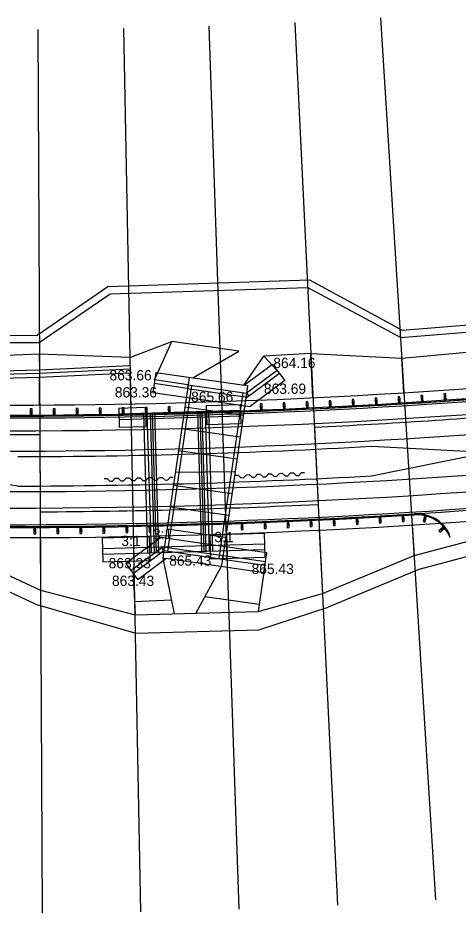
# Model space of a CAD drawing. Extents: x 223098 to 226975, y 386666 to 387582.
# Drawn here: x 223877.2 to 223996.7, y 387140.9 to 387384.1 of the extents above; entities that cross this region are included whole.
import ezdxf

# ---------------------------------------------------------------- set-up
doc = ezdxf.new("R2010")
doc.units = 0
for name, color, linetype in [('_CIVIL_CONSTRUCTION', 7, 'Continuous'), ('AP_X_Airspace', 7, 'Continuous'), ('BD_X_Building', 7, 'Continuous'), ('Default', 7, 'Continuous'), ('DR_X_Ditch', 7, 'Continuous'), ('DR_X_Erosion_Control', 7, 'Continuous'), ('DR_X_Headwall', 7, 'Continuous'), ('PF_X_Ground_Line', 7, 'Continuous'), ('PV_X_COP', 7, 'Continuous'), ('PV_X_Driveway', 7, 'Continuous'), ('PV_X_Shoulder', 7, 'Continuous'), ('PV_X_Shoulder_Aggregate', 7, 'Continuous'), ('RW_X_CL_100_Distances', 7, 'Continuous'), ('SV_X_Toe_of_Slope', 7, 'Continuous'), ('SV_X_Top_of_Bank', 7, 'Continuous'), ('UT_X_Gas_Cells', 7, 'Continuous'), ('UT_X_Water_Cells', 7, 'Continuous'), ('VG_X_Cells', 7, 'Continuous')]:
    doc.layers.add(name, color=color, linetype=linetype)

msp = doc.modelspace()

# ---------------------------------------------------------------- linework, layer by layer
at = {"layer": '_CIVIL_CONSTRUCTION'}
for p, q in [((223904.6, 387278.11), (223911.84, 387278.32)), ((223904.6, 387278.11), (223904.75, 387272.92)), ((223904.64, 387276.55), (223937.63, 387277.5)), ((223911.84, 387278.32), (223911.99, 387273.13)), ((223925.97, 387277.16), (223927.07, 387239.23)), ((223926.63, 387277.18), (223927.73, 387239.25)), ((223927.18, 387277.2), (223928.27, 387239.27)), ((223928.01, 387277.22), (223929.11, 387239.29)), ((223928.34, 387278.8), (223937.58, 387279.06)), ((223928.34, 387278.8), (223928.49, 387273.61)), ((223928.97, 387277.25), (223930.07, 387239.32)), ((223937.58, 387279.06), (223937.73, 387273.88)), ((223904.69, 387275.05), (223937.67, 387276)), ((223911.3, 387276.74), (223912.4, 387238.81)), ((223912.26, 387276.77), (223913.36, 387238.84)), ((223913.09, 387276.79), (223914.19, 387238.86)), ((223913.64, 387276.81), (223914.74, 387238.88)), ((223914.3, 387276.83), (223915.4, 387238.9)), ((223904.75, 387272.92), (223911.99, 387273.13)), ((223928.49, 387273.61), (223937.73, 387273.88)), ((223900.12, 387242.83), (223912.86, 387243.2)), ((223912.86, 387243.2), (223913.05, 387236.7)), ((223929.35, 387243.68), (223944.1, 387244.1)), ((223929.35, 387243.68), (223929.54, 387237.18)), ((223944.1, 387244.1), (223944.28, 387237.61)), ((223900.12, 387242.83), (223900.3, 387236.33)), ((223900.2, 387239.96), (223944.18, 387241.23)), ((223900.24, 387238.46), (223944.22, 387239.73)), ((223900.3, 387236.33), (223913.05, 387236.7)), ((223929.54, 387237.18), (223944.28, 387237.61))]:
    msp.add_line(p, q, dxfattribs=at)
at = {"layer": 'AP_X_Airspace'}
for points in [[(223936.25, 387259.88), (223937, 387259.91), (223937.78, 387259.19), (223938.53, 387259.22), (223939.25, 387260), (223940, 387260.03), (223940.78, 387259.31), (223941.53, 387259.34), (223942.25, 387260.12), (223943, 387260.15), (223943.77, 387259.43), (223944.52, 387259.46), (223945.24, 387260.24), (223945.99, 387260.27)], [(223945.24, 387260.24), (223945.99, 387260.27), (223946.77, 387259.55), (223947.52, 387259.58), (223948.24, 387260.36), (223948.99, 387260.39), (223949.77, 387259.67), (223950.52, 387259.7), (223951.24, 387260.48), (223951.99, 387260.51), (223952.77, 387259.79), (223953.52, 387259.82), (223954.24, 387260.6), (223954.99, 387260.63)], [(223900.66, 387259.01), (223901.41, 387259.02), (223902.17, 387258.29), (223902.92, 387258.3), (223903.66, 387259.07), (223904.41, 387259.08), (223905.17, 387258.34), (223905.92, 387258.36), (223906.66, 387259.12), (223907.41, 387259.14), (223908.17, 387258.4), (223908.92, 387258.41), (223909.66, 387259.18), (223910.41, 387259.19)], [(223909.66, 387259.18), (223910.41, 387259.19), (223911.17, 387258.46), (223911.92, 387258.47), (223912.66, 387259.23), (223913.41, 387259.25), (223914.17, 387258.51), (223914.92, 387258.53), (223915.66, 387259.29), (223916.41, 387259.3), (223917.17, 387258.57), (223917.92, 387258.58), (223918.66, 387259.35), (223919.41, 387259.36)]]:
    msp.add_lwpolyline(points, dxfattribs=at)
at = {"layer": 'BD_X_Building'}
for p, q in [((223883.03, 387295.94), (223902.27, 387309.15)), ((223902.27, 387309.15), (223955.87, 387310.88)), ((223981.08, 387297.25), (223955.87, 387310.88)), ((223981.08, 387297.25), (224104.98, 387307.24)), ((223809.49, 387295.84), (223883.03, 387295.94))]:
    msp.add_line(p, q, dxfattribs=at)
at = {"layer": 'Default'}
for p, q in [((223975.67, 387384.08), (223990.61, 387144.55)), ((223937.25, 387141.98), (223929.15, 387381.85)), ((223952.42, 387382.8), (223963.94, 387143.08)), ((223882.59, 387380.94), (223883.83, 387140.94)), ((223905.87, 387381.23), (223910.54, 387141.27))]:
    msp.add_line(p, q, dxfattribs=at)
at = {"layer": 'DR_X_Ditch'}
for p, q in [((223963.27, 387247.89), (223962.82, 387246.87)), ((223969.01, 387248.19), (223969.56, 387247.22)), ((223969.51, 387248.22), (223969.06, 387247.19)), ((223975.25, 387248.54), (223975.81, 387247.57)), ((223975.75, 387248.56), (223975.31, 387247.54)), ((223981.49, 387248.9), (223982.05, 387247.94)), ((223981.99, 387248.94), (223981.55, 387247.91)), ((223988.11, 387248.77), (223987.38, 387247.92)), ((223987.63, 387248.89), (223987.87, 387247.8)), ((223881.54, 387245.65), (223882.05, 387244.66)), ((223882.04, 387245.66), (223881.55, 387244.65)), ((223887.79, 387245.69), (223888.3, 387244.7)), ((223888.29, 387245.69), (223887.8, 387244.69)), ((223894.04, 387245.75), (223894.55, 387244.76)), ((223894.54, 387245.76), (223894.05, 387244.75)), ((223900.29, 387245.83), (223900.81, 387244.84)), ((223900.79, 387245.84), (223900.31, 387244.83)), ((223906.54, 387245.94), (223907.06, 387244.95)), ((223907.04, 387245.94), (223906.56, 387244.94)), ((223912.79, 387246.06), (223913.31, 387245.07)), ((223913.29, 387246.07), (223912.81, 387245.06)), ((223937.79, 387246.79), (223938.32, 387245.8)), ((223938.29, 387246.8), (223937.82, 387245.79)), ((223944.03, 387247.02), (223944.57, 387246.04)), ((223944.53, 387247.04), (223944.07, 387246.02)), ((223950.28, 387247.28), (223950.82, 387246.3)), ((223950.78, 387247.3), (223950.32, 387246.28)), ((223956.52, 387247.56), (223957.07, 387246.59)), ((223957.02, 387247.58), (223956.57, 387246.56)), ((223962.77, 387247.86), (223963.32, 387246.89)), ((223993.09, 387245.45), (223992, 387245.2)), ((223992.77, 387245.84), (223992.32, 387244.81)), ((223994.51, 387242.97), (223994.41, 387243.9))]:
    msp.add_line(p, q, dxfattribs=at)
for points in [[(223962.82, 387246.87), (223963.32, 387246.89), (223963.27, 387247.89), (223962.77, 387247.86)], [(223969.06, 387247.19), (223969.56, 387247.22), (223969.51, 387248.22), (223969.01, 387248.19)], [(223975.31, 387247.54), (223975.81, 387247.57), (223975.75, 387248.56), (223975.25, 387248.54)], [(223981.55, 387247.91), (223982.05, 387247.94), (223981.99, 387248.94), (223981.49, 387248.9)], [(223981.59, 387247.24), (223982.09, 387247.27), (223982.05, 387247.94), (223981.55, 387247.91)], [(223987.22, 387247.28), (223987.7, 387247.15), (223987.87, 387247.8), (223987.38, 387247.92)], [(223987.38, 387247.92), (223987.87, 387247.8), (223988.11, 387248.77), (223987.63, 387248.89)], [(223881.55, 387244.65), (223882.05, 387244.66), (223882.04, 387245.66), (223881.54, 387245.65)], [(223887.8, 387244.69), (223888.3, 387244.7), (223888.29, 387245.69), (223887.79, 387245.69)], [(223894.05, 387244.75), (223894.55, 387244.76), (223894.54, 387245.76), (223894.04, 387245.75)], [(223900.31, 387244.83), (223900.81, 387244.84), (223900.79, 387245.84), (223900.29, 387245.83)], [(223906.56, 387244.94), (223907.06, 387244.95), (223907.04, 387245.94), (223906.54, 387245.94)], [(223912.81, 387245.06), (223913.31, 387245.07), (223913.29, 387246.07), (223912.79, 387246.06)], [(223937.82, 387245.79), (223938.32, 387245.8), (223938.29, 387246.8), (223937.79, 387246.79)], [(223937.85, 387245.12), (223938.35, 387245.14), (223938.32, 387245.8), (223937.82, 387245.79)], [(223944.07, 387246.02), (223944.57, 387246.04), (223944.53, 387247.04), (223944.03, 387247.02)], [(223944.1, 387245.36), (223944.6, 387245.38), (223944.57, 387246.04), (223944.07, 387246.02)], [(223950.32, 387246.28), (223950.82, 387246.3), (223950.78, 387247.3), (223950.28, 387247.28)], [(223950.35, 387245.62), (223950.85, 387245.64), (223950.82, 387246.3), (223950.32, 387246.28)], [(223956.57, 387246.56), (223957.07, 387246.59), (223957.02, 387247.58), (223956.52, 387247.56)], [(223956.6, 387245.9), (223957.1, 387245.92), (223957.07, 387246.59), (223956.57, 387246.56)], [(223962.85, 387246.2), (223963.35, 387246.22), (223963.32, 387246.89), (223962.82, 387246.87)], [(223969.1, 387246.52), (223969.6, 387246.55), (223969.56, 387247.22), (223969.06, 387247.19)], [(223975.35, 387246.87), (223975.85, 387246.9), (223975.81, 387247.57), (223975.31, 387247.54)], [(223992, 387245.2), (223992.32, 387244.81), (223993.09, 387245.45), (223992.77, 387245.84)], [(223881.55, 387243.99), (223882.05, 387243.99), (223882.05, 387244.66), (223881.55, 387244.65)], [(223887.8, 387244.02), (223888.3, 387244.03), (223888.3, 387244.7), (223887.8, 387244.69)], [(223894.06, 387244.08), (223894.56, 387244.09), (223894.55, 387244.76), (223894.05, 387244.75)], [(223900.32, 387244.17), (223900.82, 387244.17), (223900.81, 387244.84), (223900.31, 387244.83)], [(223906.57, 387244.27), (223907.07, 387244.28), (223907.06, 387244.95), (223906.56, 387244.94)], [(223912.83, 387244.4), (223913.33, 387244.41), (223913.31, 387245.07), (223912.81, 387245.06)], [(223991.49, 387244.77), (223991.81, 387244.38), (223992.32, 387244.81), (223992, 387245.2)]]:
    msp.add_lwpolyline(points, close=True, dxfattribs=at)
for centre, radius, start, end in [((223874.12, 389011.68), 1766.04, 267.16046, 273.59506), ((223874.12, 389011.68), 1765.76, 267.16046, 273.59495), ((223985.47, 387239.41), 10, 26.6312, 93.595), ((223985.47, 387239.41), 9.72, 21.457, 93.595)]:
    msp.add_arc(centre, radius, start, end, dxfattribs=at)
at = {"layer": 'DR_X_Erosion_Control'}
for p, q in [((223882.02, 387224.88), (223909.22, 387216.93)), ((223942.59, 387217.86), (223961.4, 387224.07)), ((223909.22, 387216.93), (223942.59, 387217.86))]:
    msp.add_line(p, q, dxfattribs=at)
for points in [[(223784.61, 387295.04), (223809.49, 387297.84), (223882.41, 387297.94), (223901.62, 387311.13), (223956.35, 387312.9), (223981.51, 387299.29), (224105.08, 387309.26), (224183.43, 387294.86)], [(224029.67, 387236.44), (224009.82, 387240.6), (223986.06, 387234.3), (223961.4, 387224.07)], [(223882.02, 387224.88), (223857.12, 387236.46), (223832.67, 387236.64), (223807.35, 387237.15), (223782.08, 387237.65), (223757.07, 387238.34)]]:
    msp.add_lwpolyline(points, dxfattribs=at)
at = {"layer": 'DR_X_Headwall'}
msp.add_lwpolyline([(223907.67, 387288.69), (223883.07, 387287.49), (223858.44, 387286.89), (223833.81, 387286.93), (223809.14, 387286.48), (223784.41, 387286.67), (223759.3, 387285.04)], dxfattribs=at)
at = {"layer": 'PF_X_Ground_Line'}
msp.add_line((223973.16, 387267.73), (224045.07, 387264.09), dxfattribs=at)
for radius, start, end in [(1736.26, 268.92281, 274.61725), (1745.26, 268.92281, 274.61725), (1746.76, 270.10137, 273.25028)]:
    msp.add_arc((223874.12, 389011.68), radius, start, end, dxfattribs=at)
at = {"layer": 'PV_X_COP'}
for p, q in [((223924.68, 387286.34), (223937.23, 387293.53)), ((223938.54, 387284.34), (223944, 387292.22)), ((223916.59, 387237.33), (223919.65, 387222.23)), ((223932.42, 387235.04), (223925.55, 387222.39))]:
    msp.add_line(p, q, dxfattribs=at)
at = {"layer": 'PV_X_Driveway'}
for p, q in [((223968.52, 387278.77), (223967.97, 387279.74)), ((223968.02, 387278.74), (223968.47, 387279.77)), ((223974.76, 387279.12), (223974.2, 387280.09)), ((223974.26, 387279.09), (223974.7, 387280.12)), ((223981, 387279.49), (223980.44, 387280.46)), ((223980.5, 387279.46), (223980.94, 387280.49)), ((223987.23, 387279.89), (223986.67, 387280.86)), ((223986.73, 387279.86), (223987.17, 387280.89)), ((223993.47, 387280.31), (223992.9, 387281.27)), ((223992.97, 387280.27), (223993.4, 387281.31)), ((223881.08, 387276.21), (223880.58, 387277.21)), ((223880.58, 387276.21), (223881.08, 387277.21)), ((223887.33, 387276.25), (223886.82, 387277.25)), ((223886.83, 387276.25), (223887.32, 387277.25)), ((223893.58, 387276.31), (223893.07, 387277.3)), ((223893.08, 387276.3), (223893.57, 387277.31)), ((223899.83, 387276.39), (223899.31, 387277.38)), ((223899.33, 387276.38), (223899.81, 387277.39)), ((223906.07, 387276.49), (223905.56, 387277.49)), ((223905.57, 387276.49), (223906.06, 387277.49)), ((223912.32, 387276.62), (223911.8, 387277.61)), ((223911.82, 387276.61), (223912.3, 387277.62)), ((223918.57, 387276.77), (223918.04, 387277.76)), ((223918.07, 387276.76), (223918.54, 387277.77)), ((223943.55, 387277.59), (223943.01, 387278.57)), ((223943.05, 387277.57), (223943.51, 387278.59)), ((223949.8, 387277.85), (223949.25, 387278.83)), ((223949.3, 387277.83), (223949.75, 387278.85)), ((223956.04, 387278.13), (223955.49, 387279.11)), ((223955.54, 387278.11), (223955.99, 387279.13)), ((223962.28, 387278.44), (223961.73, 387279.41)), ((223961.78, 387278.42), (223962.23, 387279.44))]:
    msp.add_line(p, q, dxfattribs=at)
for points in [[(223993.35, 387281.97), (223992.85, 387281.94), (223992.9, 387281.27), (223993.4, 387281.31)], [(223949.72, 387279.52), (223949.22, 387279.49), (223949.25, 387278.83), (223949.75, 387278.85)], [(223955.96, 387279.8), (223955.46, 387279.78), (223955.49, 387279.11), (223955.99, 387279.13)], [(223962.19, 387280.11), (223961.7, 387280.08), (223961.73, 387279.41), (223962.23, 387279.44)], [(223968.43, 387280.43), (223967.93, 387280.41), (223967.97, 387279.74), (223968.47, 387279.77)], [(223968.47, 387279.77), (223967.97, 387279.74), (223968.02, 387278.74), (223968.52, 387278.77)], [(223974.66, 387280.78), (223974.16, 387280.76), (223974.2, 387280.09), (223974.7, 387280.12)], [(223974.7, 387280.12), (223974.2, 387280.09), (223974.26, 387279.09), (223974.76, 387279.12)], [(223980.89, 387281.16), (223980.4, 387281.13), (223980.44, 387280.46), (223980.94, 387280.49)], [(223980.94, 387280.49), (223980.44, 387280.46), (223980.5, 387279.46), (223981, 387279.49)], [(223987.12, 387281.55), (223986.63, 387281.52), (223986.67, 387280.86), (223987.17, 387280.89)], [(223987.17, 387280.89), (223986.67, 387280.86), (223986.73, 387279.86), (223987.23, 387279.89)], [(223993.4, 387281.31), (223992.9, 387281.27), (223992.97, 387280.27), (223993.47, 387280.31)], [(223881.07, 387277.88), (223880.57, 387277.88), (223880.58, 387277.21), (223881.08, 387277.21)], [(223881.08, 387277.21), (223880.58, 387277.21), (223880.58, 387276.21), (223881.08, 387276.21)], [(223887.32, 387277.92), (223886.82, 387277.91), (223886.82, 387277.25), (223887.32, 387277.25)], [(223887.32, 387277.25), (223886.82, 387277.25), (223886.83, 387276.25), (223887.33, 387276.25)], [(223893.56, 387277.98), (223893.06, 387277.97), (223893.07, 387277.3), (223893.57, 387277.31)], [(223893.57, 387277.31), (223893.07, 387277.3), (223893.08, 387276.3), (223893.58, 387276.31)], [(223899.8, 387278.06), (223899.3, 387278.05), (223899.31, 387277.38), (223899.81, 387277.39)], [(223899.81, 387277.39), (223899.31, 387277.38), (223899.33, 387276.38), (223899.83, 387276.39)], [(223906.04, 387278.16), (223905.54, 387278.15), (223905.56, 387277.49), (223906.06, 387277.49)], [(223906.06, 387277.49), (223905.56, 387277.49), (223905.57, 387276.49), (223906.07, 387276.49)], [(223912.29, 387278.29), (223911.79, 387278.28), (223911.8, 387277.61), (223912.3, 387277.62)], [(223912.3, 387277.62), (223911.8, 387277.61), (223911.82, 387276.61), (223912.32, 387276.62)], [(223918.53, 387278.44), (223918.03, 387278.42), (223918.04, 387277.76), (223918.54, 387277.77)], [(223918.54, 387277.77), (223918.04, 387277.76), (223918.07, 387276.76), (223918.57, 387276.77)], [(223943.49, 387279.26), (223942.99, 387279.24), (223943.01, 387278.57), (223943.51, 387278.59)], [(223943.51, 387278.59), (223943.01, 387278.57), (223943.05, 387277.57), (223943.55, 387277.59)], [(223949.75, 387278.85), (223949.25, 387278.83), (223949.3, 387277.83), (223949.8, 387277.85)], [(223955.99, 387279.13), (223955.49, 387279.11), (223955.54, 387278.11), (223956.04, 387278.13)], [(223962.23, 387279.44), (223961.73, 387279.41), (223961.78, 387278.42), (223962.28, 387278.44)]]:
    msp.add_lwpolyline(points, close=True, dxfattribs=at)
for radius, start in [(1735.48, 269.08669), (1735.76, 269.08671)]:
    msp.add_arc((223874.12, 389011.68), radius, start, 274.7899, dxfattribs=at)
at = {"layer": 'PV_X_Shoulder'}
for p, q in [((223914.32, 387285.74), (223919.02, 387296.16)), ((223937.23, 387293.53), (223919.02, 387296.16)), ((223944, 387292.22), (223947.59, 387288.31)), ((223944.27, 387235.43), (223942.45, 387222.86)), ((223908.52, 387233.22), (223909.08, 387221.93)), ((223909.08, 387221.93), (223942.45, 387222.86))]:
    msp.add_line(p, q, dxfattribs=at)
at = {"layer": 'PV_X_Shoulder_Aggregate'}
for p, q in [((223946.34, 387289.98), (223938.76, 387284.31)), ((223946.34, 387289.98), (223949.64, 387285.57)), ((223914.62, 387287.8), (223913.84, 387282.36)), ((223914.62, 387287.8), (223938.76, 387284.31)), ((223947.59, 387288.31), (223939.31, 387282.12)), ((223948.19, 387287.51), (223939.58, 387281.07)), ((223923.17, 387283.45), (223914.18, 387284.75)), ((223923.31, 387284.44), (223914.32, 387285.74)), ((223923.4, 387284.43), (223916.88, 387239.39)), ((223923.31, 387284.44), (223923.17, 387283.45)), ((223923.31, 387284.44), (223939.31, 387282.12)), ((223923.69, 387286.49), (223923.4, 387284.43)), ((223949.64, 387285.57), (223940.23, 387278.54)), ((223913.84, 387282.36), (223940.23, 387278.54)), ((223924.39, 387284.28), (223917.87, 387239.25)), ((223923.17, 387283.45), (223939.58, 387281.07)), ((223938.24, 387282.28), (223931.73, 387237.25)), ((223939.23, 387282.14), (223932.72, 387237.1)), ((223938.76, 387284.31), (223939.53, 387284.2)), ((223939.31, 387282.12), (223939.17, 387281.13)), ((223939.53, 387284.2), (223939.23, 387282.14)), ((223939.31, 387282.12), (223939.91, 387281.32)), ((223922.54, 387278.49), (223938.37, 387276.2)), ((223921.68, 387272.55), (223937.51, 387270.26)), ((223920.82, 387266.61), (223936.66, 387264.32)), ((223919.96, 387260.67), (223936.15, 387260.86)), ((223919.46, 387257.21), (223935.3, 387254.92)), ((223918.6, 387251.27), (223934.44, 387248.98)), ((223917.74, 387245.33), (223933.58, 387243.04)), ((223906.48, 387235.96), (223915.89, 387242.99)), ((223944.75, 387238.82), (223915.89, 387242.99)), ((223907.92, 387234.02), (223916.53, 387240.46)), ((223908.52, 387233.22), (223916.8, 387239.41)), ((223916.8, 387239.41), (223916.2, 387240.21)), ((223916.53, 387240.46), (223932.94, 387238.08)), ((223916.88, 387239.39), (223916.59, 387237.33)), ((223916.8, 387239.41), (223916.94, 387240.4)), ((223916.8, 387239.41), (223932.8, 387237.09)), ((223943.97, 387233.37), (223944.75, 387238.82)), ((223909.77, 387231.55), (223906.48, 387235.96)), ((223909.77, 387231.55), (223917.36, 387237.22)), ((223916.59, 387237.33), (223917.36, 387237.22)), ((223943.97, 387233.37), (223917.36, 387237.22)), ((223932.72, 387237.1), (223932.42, 387235.04)), ((223932.8, 387237.09), (223932.94, 387238.08)), ((223932.8, 387237.09), (223944.27, 387235.43)), ((223932.94, 387238.08), (223944.41, 387236.42))]:
    msp.add_line(p, q, dxfattribs=at)
at = {"layer": 'RW_X_CL_100_Distances'}
for p, q in [((223973.18, 387259.72), (224043.74, 387274.01)), ((223877.23, 387256.92), (223805.97, 387267.25))]:
    msp.add_line(p, q, dxfattribs=at)
for radius, start, end in [(1756.26, 268.92281, 274.61725), (1754.76, 270.10137, 273.23592), (1765.26, 268.92281, 274.61725)]:
    msp.add_arc((223874.12, 389011.68), radius, start, end, dxfattribs=at)
at = {"layer": 'SV_X_Toe_of_Slope'}
for p, q in [((223907.61, 387291.88), (223919.02, 387296.16)), ((223883.04, 387292.77), (223883.07, 387288.49)), ((223907.61, 387291.88), (223907.65, 387289.69)), ((223956.73, 387292.95), (223944, 387292.22)), ((223957.31, 387280.92), (223956.73, 387292.95)), ((223956.73, 387292.95), (223981.43, 387291.68)), ((223982.02, 387282.28), (223981.43, 387291.68)), ((223907.86, 387279.25), (223907.69, 387287.69)), ((223883.12, 387278.94), (223883.08, 387286.49)), ((223932.59, 387279.91), (223932.52, 387282.1)), ((223984.26, 387246.35), (223984.77, 387238.1)), ((223908.56, 387243.25), (223908.73, 387234.62)), ((223933.81, 387243.93), (223934.01, 387237.93)), ((223959.04, 387244.96), (223959.87, 387227.77)), ((223883.3, 387242.94), (223883.38, 387228.66)), ((223908.9, 387225.54), (223918.88, 387226.04)), ((223942.72, 387224.75), (223927.99, 387226.88)), ((223942.45, 387222.86), (223959.87, 387227.77))]:
    msp.add_line(p, q, dxfattribs=at)
for points in [[(223907.61, 387291.88), (223883.04, 387292.77), (223858.49, 387291.72), (223833.93, 387291.94), (223809.32, 387291.17), (223784.63, 387291.04)], [(223981.43, 387291.68), (224005.94, 387293.96), (224031.06, 387291.22)], [(223784.46, 387287.67), (223809.14, 387287.48), (223833.8, 387287.93), (223858.43, 387287.89), (223883.03, 387288.49), (223907.65, 387289.69)], [(223784.36, 387285.66), (223784.44, 387285.67), (223809.15, 387285.48), (223833.82, 387285.93), (223858.46, 387285.89), (223883.11, 387286.49), (223907.69, 387287.69)], [(223959.87, 387227.77), (223984.77, 387238.1), (224009.72, 387244.71), (224030.49, 387240.35)], [(223757.18, 387242.34), (223782.18, 387241.65), (223807.43, 387241.15), (223832.73, 387240.64), (223858.02, 387240.45), (223883.38, 387228.66), (223909.08, 387221.93)]]:
    msp.add_lwpolyline(points, dxfattribs=at)
for radius, start, end in [(1732.76, 268.9748, 274.7899), (1768.76, 267.16046, 274.40616)]:
    msp.add_arc((223874.12, 389011.68), radius, start, end, dxfattribs=at)
at = {"layer": 'UT_X_Gas_Cells'}
for p, q in [((223958.7, 387251.95), (223958.9, 387247.96)), ((223883.27, 387249.94), (223883.29, 387245.94))]:
    msp.add_line(p, q, dxfattribs=at)
for radius, start, end in [(1735.76, 268.661, 274.7899), (1765.76, 270.29731, 272.75178)]:
    msp.add_arc((223874.12, 389011.68), radius, start, end, dxfattribs=at)
at = {"layer": 'UT_X_Water_Cells'}
for radius, start in [(1760.76, 267.16046), (1765.76, 268.661)]:
    msp.add_arc((223874.12, 389011.68), radius, start, 274.7899, dxfattribs=at)
at = {"layer": 'VG_X_Cells'}
for p, q in [((223957.7, 387272.93), (223958.7, 387251.95)), ((223883.16, 387270.94), (223883.27, 387249.94))]:
    msp.add_line(p, q, dxfattribs=at)
for radius, start, end in [(1739.76, 267.16046, 274.7899), (1740.76, 272.75178, 274.7899), (1740.76, 267.16046, 270.29731), (1761.76, 270.29731, 272.75178)]:
    msp.add_arc((223874.12, 389011.68), radius, start, end, dxfattribs=at)

# ---------------------------------------------------------------- texts
at = {"layer": 'SV_X_Top_of_Bank'}
for s, p in [('864.16', (223946.55, 387288.98)), ('863.66', (223902.09, 387285.63)), ('863.69', (223944, 387281.97)), ('863.36', (223903.53, 387281)), ('865.66', (223924.24, 387279.77)), ('3:1', (223905.3, 387240.66)), ('3:1', (223913.86, 387242.51)), ('3:1', (223930.55, 387241.69)), ('865.43', (223918.29, 387235.3)), ('863.33', (223901.86, 387234.59)), ('865.43', (223940.65, 387233.04)), ('863.43', (223902.76, 387229.8))]:
    msp.add_text(s, height=2.8, dxfattribs=at).set_placement(p)

doc.saveas('drawing.dxf')
